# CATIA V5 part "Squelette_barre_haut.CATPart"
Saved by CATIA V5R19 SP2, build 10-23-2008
Part number: squelette_barre_haut
Publications: "Point.4"
Bounding box of the stored display mesh (mm): x -20 to 20, y -770 to -294, z 80 to 140
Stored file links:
  C:\Users\Pauline\Desktop\CFAO_Catia\Compte_rendu\pmayet_assemblage_animation4\Squelette_barre_haut.CATPart
  C:\Users\Pauline\Desktop\CFAO_Catia\Compte_rendu\pmayet_assemblage_animation4\pmayet_assemblage_animation.CATProduct
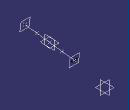
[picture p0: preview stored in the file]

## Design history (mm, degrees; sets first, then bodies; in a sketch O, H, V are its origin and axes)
Set1
  Point1: linked copy from another document
  Point2: linked copy from another document
Set2
  Line1: type PtPt, FirstPoint Point1, SecondPoint Point2
  Line2: type PtDir, RefPoint Point2, Direction yz-plane, Start -20, End 20
  Plane1: type 2Lines, Element1 Line1, Element2 Line2
  Plane2: type Normal, Curve Line1, RefPoint Point2
  Plane3: type Normal, Curve Line2, RefPoint Point3
  Point3: type OnCurve, Support Line1, Ratio 0.5
  Plane4: type OffsetPt, RefPlane Plane2, RefPoint Point1
  Point4: type OnCurve, Support Line1, Ratio 0.25
  Point5: type OnCurve, Support Line1, Ratio 0.75
Body1 (main body)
